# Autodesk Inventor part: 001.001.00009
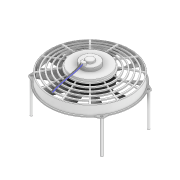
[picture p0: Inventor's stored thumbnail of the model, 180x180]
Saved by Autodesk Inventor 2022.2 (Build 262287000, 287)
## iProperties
Created: 2015-11
Part Number: 001.001.00009
Material: SolidWorks Materials|ABS
Document SubType Name: Modeling
Designer: 18907419
Density: 1.02 g/cm^3
Appearance: Default
Author: 18907419
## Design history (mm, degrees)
feature "Solido1"
feature "Solido2:1"
feature "Solido3:1"
feature "Solido4:1"
feature "Solido5:1"
node "Solido2"
node "Solido3"
node "Solido4"
node "Solido5"
node "Solido6"
